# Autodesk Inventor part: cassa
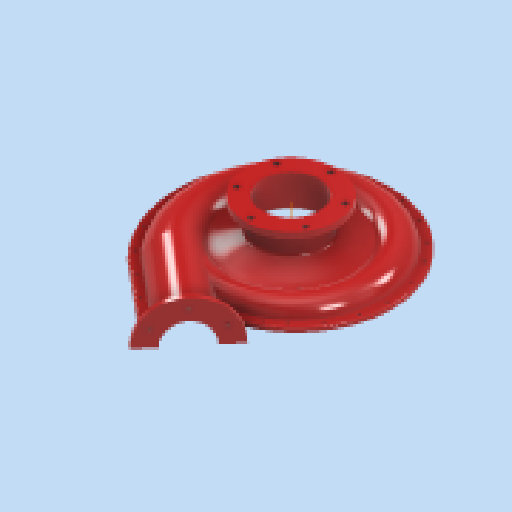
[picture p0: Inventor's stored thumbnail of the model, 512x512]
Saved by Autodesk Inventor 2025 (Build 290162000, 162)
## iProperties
Created: 2025-04
Part Number: cassa
Material: Plastica PET
Document SubType Name: Modeling
Designer: R5800u
Density: 1.541 g/cm^3
Appearance: Rosso scuro
Author: R5800u
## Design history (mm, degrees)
sketch "Schizzo31"
  geometry: C1 r 81 at (0, 0); 1 further point
  constraints: 1 centre point, 1 coincident
  dimensions: "d130" = 162 diameter of C1
feature "SupEstrusione1" sketch "Schizzo31" dims "d131" = 20, "d132" = 0
sketch "Schizzo32"
  geometry: L1 (20, -81)-(20, 81) reference; L2 (0, 81)-(20, 81) reference; L3 (0, -81)-(0, 81) reference; L4 (0, -81)-(20, -81) reference; L5 (10, 81)-(10, 91); L6 (22, 83.517)-(22, 76.086); L7 (-2, 83.517)-(-2, 76.086); L8 (0, 0)-(60.308, 0) reference; L9 (0, -81)-(20, -81); L10 (10, -81)-(10, -99); L11 (22, -76.397)-(22, -82.267); L12 (-2, -76.397)-(-2, -82.267); A1 r 14.142 centre (10, 91) between (22, 83.517) and (-2, 83.517); A2 r 19.142 centre (10, 91) between (22, 76.086) and (-2, 76.086); A3 r 20.591 centre (10, -99) between (-2, -82.267) and (22, -82.267); A4 r 25.591 centre (10, -99) between (-2, -76.397) and (22, -76.397)
  constraints: 19 end point, 8 point on circle, 5 vertical, 4 centre point, 2 coincident, 2 horizontal, 2 midpoint, 1 parallel, 1 symmetric about line
  dimensions: "d133" = 10 distance of L5.start L5.end; "d134" = 5 radial gap between concentric circles of A1 A2; "d135" = 2 distance between parallel lines of L1 L6; "d136" = 2 distance between parallel lines of L7 L3; "d137" = 14.14214 radius of A1; "d138" = 18 distance of L10.start L10.end; "d139" = 5 radial gap between concentric circles of A3 A4; "d140" = 2 distance between parallel lines of L12 L3; "d141" = 2 distance between parallel lines of L1 L11
sketch "Schizzo33"
  geometry: L1 (81, 20)-(-81, 20) reference; L2 (81, 0)-(81, 20) reference; L3 (81, 0)-(-81, 0) reference; L4 (-81, 0)-(-81, 20) reference; L5 (81, 10)-(95, 10); L6 (-81, 10)-(-103, 10); L7 (82.671, 22)-(76.317, 22); L8 (82.671, -2)-(76.317, -2); L9 (-76.417, 22)-(-82.024, 22); L10 (-76.417, -2)-(-82.024, -2); A1 r 17.205 centre (95, 10) between (82.671, -2) and (82.671, 22); A2 r 24.166 centre (-103, 10) between (-82.024, 22) and (-82.024, -2); A3 r 22.205 centre (95, 10) between (76.317, -2) and (76.317, 22); A4 r 29.166 centre (-103, 10) between (-76.417, 22) and (-76.417, -2); 1 further point
  constraints: 14 end point, 9 point on circle, 4 centre point, 4 point on line, 2 coincident, 2 horizontal, 2 midpoint, 1 parallel, 1 perpendicular
  dimensions: "d142" = 14 distance of L5.start L5.end; "d143" = 22 distance of L6.start L6.end; "d144" = 5 radial gap between concentric circles of A1 A3; "d145" = 5 radial gap between concentric circles of A2 A4; "d146" = 2 distance between parallel lines of L1 L9; "d147" = 2 distance between parallel lines of L10 L3; "d148" = 2 distance between parallel lines of L1 L7 (derived); "d149" = 2 distance between parallel lines of L8 L3 (derived)
node "Piano di lavoro32"
sketch "Schizzo34"
  geometry: L1 (20, -81)-(20, 81) reference; L2 (0, -81)-(0, 81) reference; L3 (0, 81)-(20, 81) reference; L4 (0, -81)-(20, -81) reference; L5 (10, -81)-(10, -107); L6 (22, -76.413)-(22, -81.86); L7 (-2, -81.86)-(-2, -76.413); A1 r 27.857 centre (10, -107) between (-2, -81.86) and (22, -81.86); A2 r 32.857 centre (10, -107) between (-2, -76.413) and (22, -76.413); 1 further point
  constraints: 7 end point, 4 point on circle, 2 centre point, 2 vertical, 1 coincident, 1 midpoint
  dimensions: "d151" = 26 distance of L5.start L5.end; "d152" = 5 radial gap between concentric circles of A1 A2; "d153" = 2 distance between parallel lines of L1 L6; "d154" = 2 distance between parallel lines of L2 L7
node "Piano di lavoro33"
sketch "Schizzo35"
  geometry: L1 (41.82, -0.078)-(-48.135, -0.078); L2 (103, 99)-(103, 34.826); L3 (-95, 99)-(-95.112, 30.351); A1 r 91.227 centre (-3.773, 98.851) between (0, 190) and (-95, 99); A2 r 98.916 centre (3.916, 98.839) between (-95, 99) and (0, 0); A3 r 99.078 centre (3.922, 99) between (0, 0) and (103, 99); A4 r 115.273 centre (-12.273, 99) between (103, 99) and (68.778, 180.967); 1 further point
  constraints: 8 point on circle, 6 end point, 6 tangent, 4 centre point, 1 horizontal, 1 vertical
sketch "Schizzo36"
  geometry: L1 (22, -76.397)-(22, -82.267) reference; L2 (-2, -76.397)-(-2, -82.267) reference; L3 (23, -76.957)-(23, -83.031); L4 (-3, -76.957)-(-3, -83.031); A1 r 25.591 centre (10, -99) between (-2, -76.397) and (22, -76.397) reference; A2 r 20.591 centre (10, -99) between (-2, -82.267) and (22, -82.267) reference; 1 further point
  constraints: 4 end point, 4 point on circle, 1 parallel, 1 vertical
  dimensions: "d201" = 1 distance between parallel lines of L1 L3; "d202" = 1 distance between parallel lines of L2 L4
sketch "Schizzo37"
  geometry: L1 (-76.417, 22)-(-82.024, 22) reference; L2 (-76.417, -2)-(-82.024, -2) reference; L3 (-82.628, 23)-(-76.891, 23); L4 (-82.628, -3)-(-76.891, -3); A1 r 29.166 centre (-103, 10) between (-76.417, 22) and (-76.417, -2) reference; A2 r 24.166 centre (-103, 10) between (-82.024, 22) and (-82.024, -2) reference; 1 further point
  constraints: 4 end point, 4 point on circle, 2 horizontal
  dimensions: "d199" = 1 distance between parallel lines of L1 L3; "d200" = 1 distance between parallel lines of L4 L2
loft "Loft7" sketch "Schizzo35", "Schizzo36", "Schizzo37" dims "d155" = 0, "d156" = 90 deg, "d157" = 0, "d158" = 90 deg, "d159" = 0, "d160" = 90 deg, "d161" = 0, "d162" = 90 deg, "d163" = 0, "d164" = 90 deg, "d165" = 0, "d166" = 90 deg
sketch "Schizzo38"
  geometry: L1 (25.14, 12)-(30.587, 12) reference; L2 (30.587, -12)-(25.14, -12) reference; A1 r 32.857 centre (0, 0) between (30.587, 12) and (30.587, -12) reference; A2 r 27.857 centre (0, 0) between (25.14, 12) and (25.14, -12) reference; 1 further point
sketch "Schizzo39"
  geometry: L1 (-14.914, -12)-(-7.483, -12) reference; L2 (-7.483, 12)-(-14.914, 12) reference; A1 r 19.142 centre (0, 0) between (-14.914, -12) and (-14.914, 12) reference; A2 r 19.142 centre (0, 0) between (-14.914, -12) and (-14.914, 12) reference; A3 r 14.142 centre (0, 0) between (-7.483, -12) and (-7.483, 12) reference; 1 further point
  node "Linea chiusa proiettata3"
sketch "Schizzo40"
  geometry: L1 (0, 182.517)-(0, 204.142) reference; L2 (52.619, 161.709)-(86.684, 202.306) reference; L3 (89.898, 206.137)-(49.117, 157.536) reference; A1 r 68.972 centre (25.317, 129.172) between (69.652, 182.007) and (0, 193.329); A2 r 65.893 centre (4.197, 109.327) between (49.117, 157.536) and (0, 175.086); 1 further point
  constraints: 4 point on circle, 2 centre point, 2 midpoint, 1 line through centre, 2 other
loft "Loft9" sketch "Schizzo40" dims "d173" = 0, "d174" = 90 deg, "d175" = 0, "d176" = 90 deg, "d177" = 0, "d178" = 90 deg
  node "Spigoli6"
  node "Spigoli7"
sketch "Schizzo41"
  geometry: L1 (22, -81.86)-(22, -76.413) reference; L2 (-2, -76.413)-(-2, -81.86) reference; A1 r 32.857 centre (10, -107) between (-2, -76.413) and (22, -76.413) reference; A2 r 27.857 centre (10, -107) between (-2, -81.86) and (22, -81.86) reference; 1 further point
extrude "Estrusione4" join sketch "Schizzo41" distance "d179" = 133.25; taper "d180" = 0 deg
sketch "Schizzo42"
  geometry: L1 (5.008, -4.994)-(64.281, -4.994) reference; L2 (64.281, 0.453)-(64.281, -4.994) reference; L3 (-1.203, 0.453)-(64.281, 0.453) reference; L4 (-57.207, 0.453)-(-8.066, 0.453) reference; L5 (-35.072, -4.994)-(-5.98, -4.994) reference; 2 further points
  constraints: 4 other
extrude "Estrusione5" join sketch "Schizzo42" stored distance "d181" = 133.25; taper "d182" = 0 deg
sketch "Schizzo43"
  geometry: L1 (-76.413, 22)-(-76.413, -2) reference; L2 (-81.86, 22)-(-81.86, -2) reference; A1 r 32.857 centre (-107, 10) between (-76.413, 22) and (-76.413, -2) reference; A2 r 27.857 centre (-107, 10) between (-81.86, 22) and (-81.86, -2) reference; 1 further point
extrude "Estrusione6" cut sketch "Schizzo43" stored distance "d183" = 131.5; taper "d184" = 0 deg
sketch "Schizzo45"
  geometry: L1 (0, 0)-(29.092, 0) reference; L2 (-22.135, -5.447)-(27.006, -5.447) reference; L3 (-33.897, 0)-(-27.051, 0) reference; 1 further point
  constraints: 1 horizontal alignment, 2 other
extrude "Estrusione7" join sketch "Schizzo45" distance "d185" = 23; taper "d186" = 0 deg
sketch "Schizzo46"
  geometry: L1 (-81.86, 22)-(-81.86, -2) reference; A1 r 27.857 centre (-107, 10) between (-81.86, 22) and (-81.86, -2) reference; 3 further points
  constraints: 1 coincident, 3 other
extrude "Estrusione8" cut sketch "Schizzo46" stored distance "d187" = 23; taper "d188" = 0 deg
sketch "Schizzo47"
  geometry: L1 (-76.039, -1)-(-76.039, 21.602) reference; L2 (-76.413, 22)-(-76.413, -2) reference; L3 (-76.413, 22)-(-76.413, -2) reference; C1 r 27.857 at (-107, 10); C2 r 27.857 at (-107, 10) reference; C3 r 27.857 at (-107, 10) reference; A1 r 27.857 centre (-107, 10) between (-92.729, 33.924) and (-92.729, -13.924) reference; A2 r 32.857 centre (-107, 10) between (-76.413, 22) and (-76.413, -2) reference; A3 r 32.857 centre (-107, 10) between (-76.413, 22) and (-76.413, -2) reference; 4 further points
  constraints: 2 coincident, 1 centre point, 3 other
extrude "Estrusione9" join sketch "Schizzo47" distance "d189" = 100; taper "d190" = 0 deg
node "Asse di lavoro2"
sketch "Schizzo48"
  geometry: C1 r 82 at (0, 0); 1 further point
  constraints: 1 centre point, 1 coincident
  dimensions: "d193" = 164 diameter of C1
extrude "Estrusione10" cut sketch "Schizzo48" extent not by distance; stored distance "d194" = 0; taper "d195" = 0 deg
sketch "Schizzo50"
  geometry: A1 r 27.857 centre (-107, 10) between (-92.729, 33.924) and (-92.729, -13.924) reference; A2 r 32.857 centre (-107, 10) between (-76.413, 22) and (-90.361, 38.332) reference; 7 further points
  constraints: 2 coincident, 5 other
extrude "Estrusione12" join sketch "Schizzo50" distance "d203" = 61.389; taper "d204" = 0 deg
sketch "Schizzo51"
  geometry: C1 r 198.377 at (0, 99); 1 further point
  constraints: 1 centre point, 1 coincident
extrude "Estrusione13" cut sketch "Schizzo51" extent not by distance; stored distance "d205" = 0; taper "d206" = 0 deg
sketch "Schizzo52"
  geometry: L1 (-22.487, 178.898)-(-26.521, 183.705); L2 (-30.748, 176.514)-(51.203, 245.279) reference; L3 (-26.521, 183.705)-(-42.91, 169.953); L4 (-42.91, 169.953)-(-40.893, 167.549); L5 (-40.893, 167.549)-(-22.487, 178.898); 1 further point
  constraints: 8 end point, 3 perpendicular
extrude "Estrusione14" cut sketch "Schizzo52" stored distance "d207" = 10; taper "d208" = 0 deg
fillet "Raccordo4" dims "d209" = 8.5
feature "SupEstrusione2" dims "d210" = 32, "d211" = 0
sketch "Schizzo55"
  geometry: L1 (10, -124.591)-(10, -119.591) reference; L2 (10, 176.043)-(10, 182.57) reference; L3 (21.11, 99.75)-(10, 99.75) reference; L4 (10, 99.75)-(10, 103.314) reference; L5 (22.323, 73.936)-(33.609, 37); L6 (33.609, 37)-(68.609, 37); L7 (68.609, 42)-(37.257, 42); L8 (37.257, 42)-(25.641, 79.965); L9 (68.609, 37)-(68.609, 40.539); L10 (68.609, 40.539)-(68.609, 42); L11 (0, 0)-(73.859, 0); L12 (53, 35)-(39.046, 35) reference; A1 r 7.327 centre (29.327, 76.086) between (22, 76.086) and (22.323, 73.936); A2 r 75.179 centre (100.933, 90.8) between (26.383, 81.099) and (28.669, 70.067); 8 further points; 2 other entities
  constraints: 16 end point, 4 point on circle, 3 horizontal, 2 centre point, 2 vertical alignment, 1 collinear, 1 perpendicular, 1 point on line, 14 other
  dimensions: "d216" = 35 distance of L5.end L6.end; "d217" = 5 distance between parallel lines of L6 L7; "d220" = 2 distance between parallel lines of L6 L12
revolve "Rivoluzione2" sketch "Schizzo55" stored, may be unused: angle "d218" = 360 deg
fillet "Raccordo5" dims "d219" = 8
fillet "Raccordo6" dims "d221" = 5
sketch "Schizzo56"
  geometry: L1 (-24.726, 181.566)-(-22.971, 179.475) reference; L2 (5.931, 203.727)-(-22.971, 179.475) reference; L3 (7.39, 201.988)-(5.931, 203.727) reference; L4 (10.033, 204.205)-(7.39, 201.988) reference; L5 (15.391, 287.958)-(-86.684, 202.306) reference; L6 (12.177, 291.788)-(15.391, 287.958) reference; L7 (-89.898, 206.137)-(12.177, 291.788) reference; L8 (54.417, 241.448)-(15.563, 208.846) reference; L9 (51.203, 245.279)-(54.417, 241.448) reference; L10 (-24.726, 181.566)-(51.203, 245.279) reference; L11 (13.656, 308.694)-(32.297, 286.479); L12 (32.297, 286.479)-(-78.513, 193.498); L13 (14.059, 191.919)-(5.911, 185.082); L14 (5.911, 185.082)-(4.452, 186.821); L15 (4.452, 186.821)-(-24.45, 162.569); L16 (-24.45, 162.569)-(-41.632, 183.045); L17 (-41.632, 183.045)-(52.682, 262.185); L18 (52.682, 262.185)-(71.323, 239.969); L19 (71.323, 239.969)-(42.366, 215.671); L20 (-98.044, 214.966)-(13.656, 308.694); L21 (15.391, 287.958)-(51.203, 245.279) reference; L22 (15.391, 287.958)-(4.464, 300.98); L23 (54.417, 241.448)-(62.131, 232.256); 2 further points
  constraints: 24 end point, 4 parallel, 3 point on line, 1 perpendicular, 15 other
  dimensions: "d222" = 12 distance between parallel lines of L7 L20
extrude "Estrusione15" join sketch "Schizzo56" distance "d223" = 5; taper "d224" = 0 deg
fillet "Raccordo7" dims "d225" = 5
fillet "Raccordo8" dims "d226" = 2
fillet "Raccordo9" dims "d227" = 10
fillet "Raccordo10" dims "d228" = 3
sketch "Schizzo57"
  geometry: L1 (-151.857, 10)-(-151.857, 13) reference; L2 (-134.857, 10)-(-151.857, 10) reference; L3 (-62.143, 10)-(-79.143, 10) reference; L4 (-62.143, 10)-(-62.143, 13) reference; L5 (-74.526, 15)-(-64.143, 15) reference; L6 (-149.857, 15)-(-139.474, 15) reference; L7 (-139.857, 10)-(-74.143, 10); L8 (-134.857, 10)-(-151.857, 10) reference; L9 (-107, 10)-(-151.857, 10); L10 (-107, 10)-(-105.748, 10); L11 (-107, 10)-(-52, 10); L12 (-151.857, 10)-(-162, 10); A1 r 2 centre (-149.857, 13) between (-149.857, 15) and (-151.857, 13) reference; A2 r 27.857 centre (-107, 10) between (-79.143, 10) and (-134.857, 10) reference; A3 r 2 centre (-64.143, 13) between (-62.143, 13) and (-64.143, 15) reference; A4 r 32.857 centre (-107, 10) between (-74.526, 15) and (-139.474, 15) reference; A5 r 32.857 centre (-107, 10) between (-139.474, 15) and (-139.857, 10); A6 r 55 centre (-107, 10) between (-52, 10) and (-162, 10); 4 further points
  constraints: 10 end point, 5 point on circle, 3 point on line, 2 centre point, 2 coincident, 1 collinear, 1 horizontal
  dimensions: "d229" = 110 diameter of A6
extrude "Estrusione16" join sketch "Schizzo57" distance "d230" = 6; taper "d231" = 0 deg
sketch "Schizzo58"
  geometry: C1 r 37 at (0, 0) reference; C2 r 60 at (0, 0); 1 further point
  constraints: 1 centre point, 1 coincident
  dimensions: "d232" = 120 diameter of C2
extrude "Estrusione17" join sketch "Schizzo58" distance "d233" = 8; taper "d234" = 0 deg
fillet "Raccordo11" dims "d235" = 2
fillet "Raccordo12" dims "d236" = 2
sketch "Schizzo59"
  geometry: 2 further points
  dimensions: "d237" = 52 distance of point (0, 0) point (0, -52)
hole "Foro1" sketch "Schizzo59" at (0, -52) diameter "d238" = 6.647; stored, may be unused: countersink angle "d242" = 90 deg, drill point angle "d244" = 118 deg; dims "d239" = 16, "d240" = 4, "d241" = 2, "d243" = 22.2
pattern_circular "Serie circolare1" dims angle "d246" = 360 deg
sketch "Schizzo60"
  geometry: A1 r 55 centre (-107, 10) between (-52, 10) and (-162, 10) reference; 2 further points
  dimensions: "d248" = 42 distance of point (-107, 52) A1.centre
hole "Foro2" sketch "Schizzo60" at (-107, 52) diameter "d249" = 4.917; stored, may be unused: countersink angle "d253" = 90 deg, drill point angle "d255" = 118 deg; dims "d250" = 12, "d251" = 4, "d252" = 2, "d254" = 17.1
pattern_circular "Serie circolare2" dims angle "d257" = 360 deg
sketch "Schizzo61" dims "d259" = 6
  geometry: L1 (52.639, -240.456)-(14.31, -208.294) reference; L2 (-89.652, -205.843)-(10.891, -290.209) reference; L3 (7.034, -294.806)-(-93.727, -210.257); L4 (28.504, -212.372)-(56.496, -235.86); 25 further points
  constraints: 4 end point, 4 point on line, 2 parallel, 1 midpoint, 22 other
hole "Foro3" sketch "Schizzo61" diameter "d260" = 4.3; stored, may be unused: countersink angle "d264" = 90 deg, drill point angle "d266" = 118 deg; dims "d261" = 8, "d262" = 8, "d263" = 4.6, "d265" = 8
node "Solido7"
node "Superf1"
node "Linea chiusa proiettata4"
node "Linea chiusa proiettata5"
node "Linea chiusa proiettata6"
node "Linea chiusa proiettata7"
node "Linea chiusa proiettata8"
node "Superf2"
node "Linea chiusa proiettata11"
node "Linea chiusa proiettata12"
node "Proietta spigoli di taglio1"
other parameters: "d150" = 140 deg
